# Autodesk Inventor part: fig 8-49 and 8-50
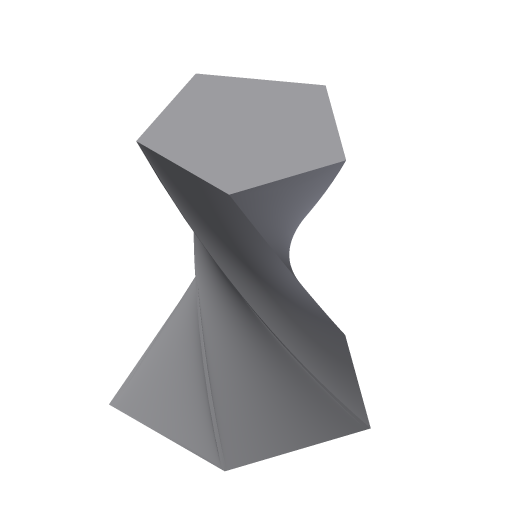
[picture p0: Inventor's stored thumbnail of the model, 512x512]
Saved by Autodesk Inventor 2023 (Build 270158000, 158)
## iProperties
Part Number: fig 8-49 and 8-50
Document SubType Name: Modeling
Created: 2002-12
Designer: deepak
Density: 1 g/cm^3
Material: Generic
Appearance: Default
Control State: 0
Master: False
Checked Out: False
Shininess: 64.0
Length Units: 11269
Angle Units: 11279
Time Units: 11290
Mass Units: 11283
Length Display Precision: 3
Angle Display Precision: 2
Compacted: True
Density: 0.0
Volumn: 0.0
Area: 0.0
PropertySet Name: Model Information
Author: deepak
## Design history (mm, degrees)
sketch "Sketch1"
  geometry: L1 (0, 21.819)-(20.751, 6.743); L2 (20.751, 6.743)-(12.825, -17.652); L3 (12.825, -17.652)-(-12.825, -17.652); L4 (-12.825, -17.652)-(-20.751, 6.743); L5 (-20.751, 6.743)-(0, 21.819); 1 further point
  constraints: 10 end point, 9 other
workplane "Work Plane1"
sketch "Sketch2"
  geometry: L1 (0, 8.24)-(7.836, 2.546); L2 (7.836, 2.546)-(4.843, -6.666); L3 (4.843, -6.666)-(-4.843, -6.666); L4 (-4.843, -6.666)-(-7.836, 2.546); L5 (-7.836, 2.546)-(0, 8.24); 1 further point
  constraints: 10 end point, 9 other
workplane "Work Plane2"
sketch "Sketch3"
  geometry: L1 (0, 17.494)-(16.637, 5.406); L2 (16.637, 5.406)-(10.283, -14.153); L3 (10.283, -14.153)-(-10.283, -14.153); L4 (-10.283, -14.153)-(-16.637, 5.406); L5 (-16.637, 5.406)-(0, 17.494); 1 further point
  constraints: 10 end point, 9 other
loft "Loft4" sketch "Sketch3" dims "d20" = 0, "d21" = 90 deg, "d22" = 0, "d23" = 90 deg, "d24" = 0, "d25" = 90 deg
body "Solid1"
other parameters: "d0" = 25, "d1" = 25
